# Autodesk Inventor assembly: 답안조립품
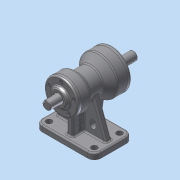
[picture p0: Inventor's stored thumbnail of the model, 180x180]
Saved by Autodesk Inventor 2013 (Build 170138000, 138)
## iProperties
Created: 2015-08
Part Number: 답안조립품
Document SubType Name: Assembly
Designer: dgall
Author: dgall
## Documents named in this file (10)
- C:\Users\dgall\Desktop\450805V1037\답안조립품.iam
- C:\Users\dgall\Desktop\450805V1037\1. 본체.ipt
- C:\Users\dgall\Desktop\450805V1037\뒤커버.ipt
- C:\Users\dgall\Desktop\450805V1037\앞커버.ipt
- C:\Users\dgall\Desktop\450805V1037\오일실 .ipt
- 오일실 .ipt
- C:\Users\dgall\Desktop\450805V1037\베어링 6203.ipt
- C:\Users\dgall\Desktop\450805V1037\베어링 6205.ipt
- C:\Users\dgall\Desktop\450805V1037\축.ipt
- C:\Users\dgall\Desktop\450805V1037\M4x0.5.ipt
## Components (11 placed, 2 different names)
1. 1. 본체:1
2. M4x0.5:1
3. M4x0.5:2
4. M4x0.5:3
5. M4x0.5:4
6. M4x0.5:5
7. M4x0.5:6
8. M4x0.5:7
9. M4x0.5:8
10. M4x0.5:9
11. M4x0.5:10
